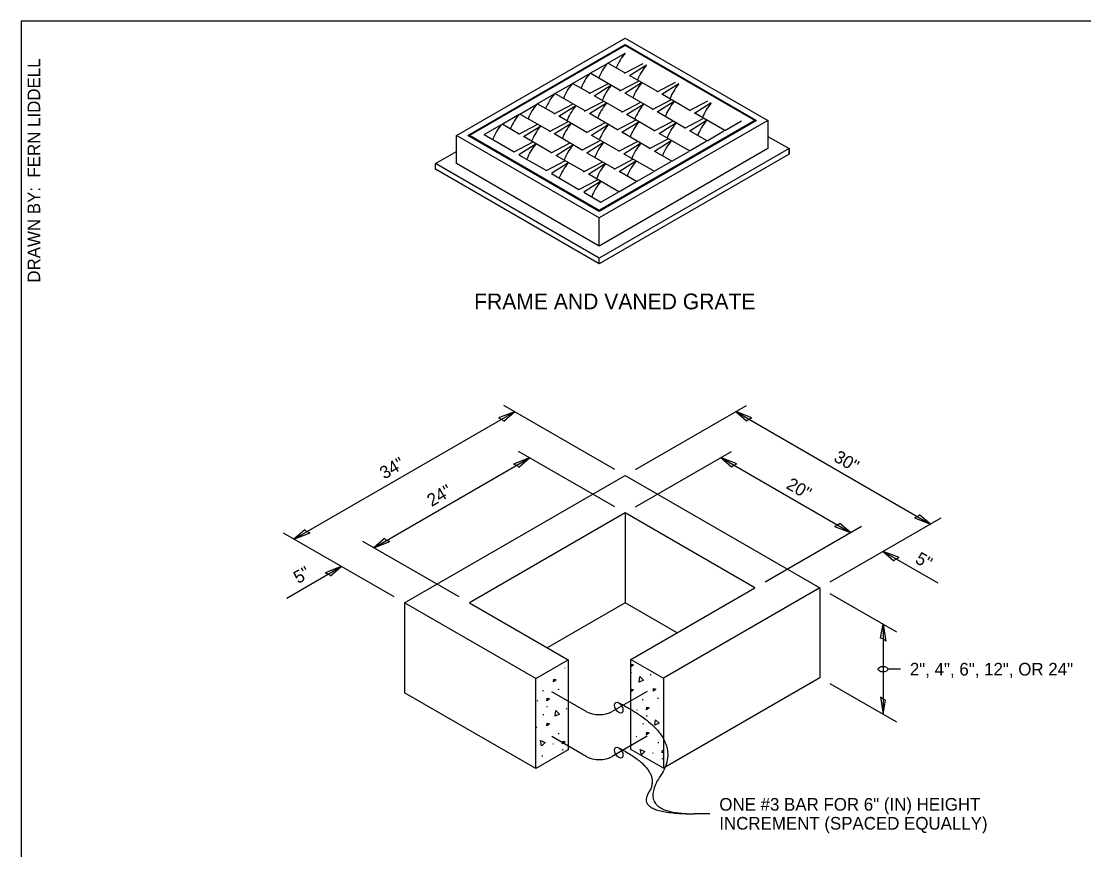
# Model space of a CAD drawing. Extents: x 99862 to 103151, y 100000 to 102076.
# Drawn here: x 99862 to 101209, y 101025 to 102076 of the extents above; entities that cross this region are included whole.
import ezdxf

# ---------------------------------------------------------------- set-up
doc = ezdxf.new("R2010")
doc.units = 0
for name, color, linetype in [('Level 1', 7, 'Continuous'), ('Level 12', 7, 'Continuous'), ('Level 13', 7, 'Continuous'), ('Level 15', 7, 'Continuous'), ('Level 17', 7, 'Continuous'), ('Level 20', 7, 'Continuous'), ('Level 3', 7, 'Continuous'), ('Level 62', 7, 'Continuous'), ('Level 8', 7, 'Continuous'), ('Level 9', 7, 'Continuous')]:
    doc.layers.add(name, color=color, linetype=linetype)

msp = doc.modelspace()

# ---------------------------------------------------------------- linework, layer by layer
at = {"layer": 'Level 1'}
for p, q in [((100347.8, 101338.4), (100627.5, 101499.9)), ((100627.5, 101499.9), (100874.3, 101357.4)), ((100627.5, 101452.4), (100430.1, 101338.4)), ((100627.5, 101452.4), (100627.5, 101395.4)), ((100792, 101357.4), (100627.5, 101452.4)), ((100627.5, 101395.4), (100627.5, 101338.4)), ((100634.8, 101266.6), (100792, 101357.4)), ((100874.3, 101357.4), (100675.9, 101242.8)), ((100874.3, 101357.4), (100874.3, 101300.4)), ((100347.8, 101338.4), (100347.8, 101281.4)), ((100514.1, 101242.4), (100347.8, 101338.4)), ((100430.1, 101338.4), (100555.3, 101266.1)), ((100627.5, 101338.4), (100528.8, 101281.4)), ((100693.3, 101300.4), (100627.5, 101338.4)), ((100874.3, 101300.4), (100874.3, 101243.4)), ((100347.8, 101281.4), (100347.8, 101224.4)), ((100874.3, 101243.4), (100675.9, 101128.9)), ((100514.1, 101128.4), (100347.8, 101224.4))]:
    msp.add_line(p, q, dxfattribs=at)
msp.add_lwpolyline([(99862, 99999.5), (103151, 99999.5), (103151, 102075.5), (99862, 102075.5)], close=True, dxfattribs=at)
at = {"layer": 'Level 12'}
for p, q in [((100627.5, 102044.7), (100430.1, 101930.7)), ((100792, 101949.7), (100627.5, 102044.7)), ((100605.6, 102022.5), (100627.3, 102035)), ((100583.2, 102009.6), (100604.9, 102022.1)), ((100627.2, 102010), (100605.6, 102022.5)), ((100626.8, 102009.8), (100650.1, 102022.1)), ((100654.3, 102019.7), (100632.9, 102006.2)), ((100560.9, 101996.7), (100582.6, 102009.2)), ((100621.3, 101987.6), (100583.2, 102009.6)), ((100668.3, 101986.3), (100633.6, 102006.3)), ((100538.5, 101983.8), (100560.2, 101996.3)), ((100582.5, 101984.2), (100560.9, 101996.7)), ((100582, 101984), (100605.4, 101996.3)), ((100609.5, 101993.9), (100588.2, 101980.4)), ((100620.8, 101987.4), (100644.2, 101999.7)), ((100648.3, 101997.3), (100627, 101983.8)), ((100667.9, 101986), (100691.3, 101998.4)), ((100695.4, 101996), (100674.1, 101982.5)), ((100516.1, 101970.9), (100537.8, 101983.4)), ((100576.6, 101961.8), (100538.5, 101983.8)), ((100576.1, 101961.6), (100599.5, 101973.9)), ((100623.6, 101960.5), (100588.9, 101980.5)), ((100662.4, 101963.9), (100627.7, 101983.9)), ((100662, 101963.6), (100685.4, 101976)), ((100689.5, 101973.6), (100668.1, 101960.1)), ((100709.5, 101962.5), (100674.8, 101982.6)), ((100709, 101962.3), (100732.4, 101974.6)), ((100493.8, 101957.9), (100515.5, 101970.5)), ((100537.7, 101958.4), (100516.1, 101970.9)), ((100537.3, 101958.1), (100560.7, 101970.5)), ((100564.8, 101968.1), (100543.5, 101954.6)), ((100603.6, 101971.5), (100582.3, 101958)), ((100623.2, 101960.2), (100646.5, 101972.5)), ((100650.7, 101970.2), (100629.3, 101956.7)), ((100703.5, 101940.1), (100668.8, 101960.2)), ((100736.5, 101972.2), (100715.2, 101958.7)), ((100471.4, 101945), (100493.1, 101957.6)), ((100531.8, 101936), (100493.8, 101957.9)), ((100531.4, 101935.7), (100554.8, 101948.1)), ((100578.9, 101934.6), (100544.2, 101954.7)), ((100578.4, 101934.4), (100601.8, 101946.7)), ((100617.7, 101938), (100583, 101958.1)), ((100792, 101949.7), (100594.6, 101835.7)), ((100617.2, 101937.8), (100640.6, 101950.1)), ((100644.7, 101947.8), (100623.4, 101934.3)), ((100664.7, 101936.7), (100630, 101956.7)), ((100664.3, 101936.5), (100687.7, 101948.8)), ((100691.8, 101946.4), (100670.5, 101932.9)), ((100703.1, 101939.9), (100726.5, 101952.2)), ((100730.6, 101949.8), (100709.3, 101936.3)), ((100753.7, 101937), (100715.9, 101958.8)), ((100753.7, 101937), (100775.1, 101949.4)), ((100792, 101949.7), (100791.9, 101948.4)), ((100448.6, 101931.9), (100470.7, 101944.7)), ((100493, 101932.6), (100471.4, 101945)), ((100492.6, 101932.3), (100516, 101944.6)), ((100520.1, 101942.3), (100498.7, 101928.8)), ((100558.9, 101945.7), (100537.5, 101932.2)), ((100605.9, 101944.3), (100584.6, 101930.8)), ((100658.8, 101914.3), (100624.1, 101934.3)), ((100708.9, 101911.2), (100671.2, 101933)), ((100731.3, 101924.1), (100710, 101936.4)), ((100731.3, 101924.1), (100752.7, 101936.5)), ((100594.6, 101835.7), (100430.1, 101930.7)), ((100430.3, 101929.4), (100430.1, 101930.7)), ((100448.6, 101931.9), (100486.6, 101909.9)), ((100486.6, 101909.9), (100510, 101922.2)), ((100514.2, 101919.9), (100492.8, 101906.3)), ((100534.1, 101908.8), (100499.4, 101928.8)), ((100533.7, 101908.6), (100557.1, 101920.9)), ((100573, 101912.2), (100538.3, 101932.3)), ((100572.5, 101912), (100595.9, 101924.3)), ((100600, 101921.9), (100578.7, 101908.4)), ((100620, 101910.9), (100585.3, 101930.9)), ((100619.6, 101910.7), (100642.9, 101923)), ((100647.1, 101920.6), (100625.7, 101907.1)), ((100658.4, 101914.1), (100681.8, 101926.4)), ((100685.9, 101924), (100664.5, 101910.5)), ((100708.9, 101911.2), (100730.3, 101923.6)), ((100492.8, 101906.3), (100527.8, 101886.2)), ((100561.2, 101918.5), (100539.9, 101905)), ((100614.1, 101888.5), (100579.4, 101908.5)), ((100664.2, 101885.4), (100626.4, 101907.2)), ((100686.6, 101898.3), (100665.2, 101910.6)), ((100686.6, 101898.3), (100708, 101910.6)), ((100527.8, 101886.2), (100551.2, 101898.5)), ((100555.3, 101896.1), (100534, 101882.6)), ((100575.3, 101885.1), (100540.6, 101905.1)), ((100574.8, 101884.8), (100598.2, 101897.1)), ((100602.3, 101894.8), (100581, 101881.3)), ((100613.6, 101888.2), (100637, 101900.6)), ((100641.1, 101898.2), (100619.8, 101884.7)), ((100664.2, 101885.4), (100685.6, 101897.7)), ((100534, 101882.6), (100568.9, 101862.4)), ((100619.5, 101859.5), (100581.7, 101881.4)), ((100641.8, 101872.5), (100620.5, 101884.8)), ((100641.8, 101872.5), (100663.2, 101884.8)), ((100568.9, 101862.4), (100592.3, 101874.7)), ((100596.4, 101872.4), (100575.1, 101858.9)), ((100619.5, 101859.5), (100640.9, 101871.9)), ((100575.1, 101858.9), (100596.7, 101846.4)), ((100596.7, 101846.4), (100618.5, 101859)), ((100594.6, 101834.5), (100594.6, 101835.7))]:
    msp.add_line(p, q, dxfattribs=at)
for centre, major_axis, ratio, start_param, end_param in [((100641.1, 102010.3), (17.8, 36.7), 0.619773, 1.161599, 1.703913), ((100618.7, 101997.4), (17.8, 36.7), 0.619773, 1.161599, 1.703913), ((100666.2, 101995.8), (17.9, 36.6), 0.569297, 1.174658, 1.709128), ((100596.4, 101984.5), (17.8, 36.7), 0.619773, 1.161599, 1.703913), ((100633, 102005), (0.64, 1.31), 0.569297, 6.243649, 7.029047), ((100574, 101971.6), (17.8, 36.7), 0.619773, 1.161599, 1.703913), ((100621.5, 101970), (17.9, 36.6), 0.569297, 1.174658, 1.709128), ((100660.3, 101973.4), (17.9, 36.6), 0.569297, 1.174658, 1.709128), ((100648.4, 101996.1), (0.64, 1.31), 0.569297, 0.745861, 1.174658), ((100707.3, 101972.1), (17.9, 36.6), 0.569297, 1.174658, 1.709128), ((100695.4, 101994.8), (0.64, 1.31), 0.569297, 0.745861, 1.174658), ((100551.6, 101958.7), (17.8, 36.7), 0.619773, 1.161599, 1.703913), ((100588.2, 101979.2), (0.64, 1.31), 0.569297, 6.243649, 7.029047), ((100627, 101982.6), (0.64, 1.31), 0.569297, 6.243649, 7.029047), ((100674.1, 101981.3), (0.64, 1.31), 0.569297, 6.243649, 7.029047), ((100701.4, 101949.7), (17.9, 36.6), 0.569297, 1.174658, 1.709128), ((100689.5, 101972.4), (0.64, 1.31), 0.569297, 0.745861, 1.174658), ((100529.3, 101945.8), (17.8, 36.7), 0.619773, 1.161599, 1.703913), ((100576.7, 101944.2), (17.9, 36.6), 0.569297, 1.174658, 1.709128), ((100615.6, 101947.6), (17.9, 36.6), 0.569297, 1.174658, 1.709128), ((100603.7, 101970.3), (0.64, 1.31), 0.569297, 0.745861, 1.174658), ((100662.6, 101946.3), (17.9, 36.6), 0.569297, 1.174658, 1.709128), ((100650.7, 101969), (0.64, 1.31), 0.569297, 0.745861, 1.174658), ((100668.2, 101958.9), (0.64, 1.31), 0.569297, 6.243649, 7.029047), ((100748.5, 101948.3), (17.9, 36.6), 0.569297, 1.174658, 1.709128), ((100736.6, 101971), (0.64, 1.31), 0.569297, 0.745861, 1.174658), ((100506.9, 101932.9), (17.8, 36.7), 0.619773, 1.161599, 1.703913), ((100543.5, 101953.4), (0.64, 1.31), 0.569297, 6.243649, 7.029047), ((100582.3, 101956.8), (0.64, 1.31), 0.569297, 6.243649, 7.029047), ((100629.4, 101955.5), (0.64, 1.31), 0.569297, 6.243649, 7.029047), ((100656.7, 101923.9), (17.9, 36.6), 0.569297, 1.174658, 1.709128), ((100644.8, 101946.5), (0.64, 1.31), 0.569297, 0.745861, 1.174658), ((100691.8, 101945.2), (0.64, 1.31), 0.569297, 0.745861, 1.174658), ((100715.2, 101957.5), (0.64, 1.31), 0.569297, 6.243649, 7.029047), ((100742.5, 101925.9), (17.9, 36.6), 0.569297, 1.174658, 1.709128), ((100730.6, 101948.6), (0.64, 1.31), 0.569297, 0.745861, 1.174658), ((100484.5, 101919.9), (17.8, 36.7), 0.619773, 1.161599, 1.714552), ((100532, 101918.4), (17.9, 36.6), 0.569297, 1.174658, 1.709128), ((100570.8, 101921.8), (17.9, 36.6), 0.569297, 1.174658, 1.709128), ((100558.9, 101944.5), (0.64, 1.31), 0.569297, 0.745861, 1.174658), ((100617.9, 101920.4), (17.9, 36.6), 0.569297, 1.174658, 1.709128), ((100606, 101943.1), (0.64, 1.31), 0.569297, 0.745861, 1.174658), ((100623.4, 101933), (0.64, 1.31), 0.569297, 6.243649, 7.029047), ((100670.5, 101931.7), (0.64, 1.31), 0.569297, 6.243649, 7.029047), ((100703.7, 101922.5), (17.9, 36.6), 0.569297, 1.174658, 1.709128), ((100709.3, 101935.1), (0.64, 1.31), 0.569297, 6.243649, 7.029047), ((100498.8, 101927.6), (0.64, 1.31), 0.569297, 6.243649, 7.029047), ((100526.1, 101895.9), (17.9, 36.6), 0.569297, 1.174658, 1.719767), ((100514.2, 101918.6), (0.64, 1.31), 0.569297, 0.745861, 1.174658), ((100537.6, 101931), (0.64, 1.31), 0.569297, 6.243649, 7.029047), ((100584.6, 101929.6), (0.64, 1.31), 0.569297, 6.243649, 7.029047), ((100612, 101898), (17.9, 36.6), 0.569297, 1.174658, 1.709128), ((100600.1, 101920.7), (0.64, 1.31), 0.569297, 0.745861, 1.174658), ((100659, 101896.7), (17.9, 36.6), 0.569297, 1.174658, 1.709128), ((100647.1, 101919.4), (0.64, 1.31), 0.569297, 0.745861, 1.174658), ((100697.8, 101900.1), (17.9, 36.6), 0.569297, 1.174658, 1.709128), ((100685.9, 101922.8), (0.64, 1.31), 0.569297, 0.745861, 1.174658), ((100573.1, 101894.6), (17.9, 36.6), 0.569297, 1.174658, 1.709128), ((100561.2, 101917.3), (0.64, 1.31), 0.569297, 0.745861, 1.174658), ((100578.7, 101907.2), (0.64, 1.31), 0.569297, 6.243649, 7.029047), ((100625.8, 101905.9), (0.64, 1.31), 0.569297, 6.243649, 7.029047), ((100664.6, 101909.3), (0.64, 1.31), 0.569297, 6.243649, 7.029047), ((100539.9, 101903.8), (0.64, 1.31), 0.569297, 6.243649, 7.029047), ((100567.2, 101872.2), (17.9, 36.6), 0.569297, 1.174658, 1.719767), ((100555.3, 101894.9), (0.64, 1.31), 0.569297, 0.745861, 1.174658), ((100614.3, 101870.9), (17.9, 36.6), 0.569297, 1.174658, 1.709128), ((100602.4, 101893.6), (0.64, 1.31), 0.569297, 0.745861, 1.174658), ((100653.1, 101874.3), (17.9, 36.6), 0.569297, 1.174658, 1.709128), ((100641.2, 101897), (0.64, 1.31), 0.569297, 0.745861, 1.174658), ((100581, 101880.1), (0.64, 1.31), 0.569297, 6.243649, 7.029047), ((100619.8, 101883.5), (0.64, 1.31), 0.569297, 6.243649, 7.029047), ((100608.4, 101848.5), (17.9, 36.6), 0.569297, 1.174658, 1.719767), ((100596.5, 101871.2), (0.64, 1.31), 0.569297, 0.745861, 1.174658)]:
    msp.add_ellipse(centre, major_axis=major_axis, ratio=ratio, start_param=start_param, end_param=end_param, dxfattribs=at)
at = {"layer": 'Level 13'}
for p, q in [((100550.8, 101256), (100551.5, 101255.5)), ((100634.8, 101249.9), (100635, 101249.7)), ((100634.9, 101250.2), (100635.6, 101249.6)), ((100659.8, 101246.7), (100659.9, 101247.9)), ((100523.6, 101226.4), (100523.7, 101227.6)), ((100543.1, 101228.1), (100543.2, 101229.3)), ((100516, 101214.9), (100516.5, 101213.9)), ((100527.8, 101207.2), (100528.5, 101206.7)), ((100528.4, 101207.1), (100529.1, 101206.6)), ((100649.9, 101214.9), (100650, 101216.2)), ((100669.4, 101216.6), (100669.5, 101217.8)), ((100524.1, 101196), (100524.1, 101197.2)), ((100553.3, 101203.6), (100553.4, 101204.8)), ((100642.3, 101203.4), (100642.8, 101202.4)), ((100654.2, 101195.7), (100654.9, 101195.2)), ((100654.7, 101195.6), (100655.5, 101195.1)), ((100514.7, 101181.1), (100515.4, 101180.6)), ((100650.4, 101184.5), (100650.5, 101185.8)), ((100543.4, 101171.9), (100543.5, 101173.1)), ((100641, 101169.6), (100641.8, 101169.1)), ((100535.8, 101160.3), (100536.3, 101159.3)), ((100547.7, 101152.6), (100548.4, 101152.1)), ((100548.2, 101152.5), (100548.9, 101152)), ((100669.8, 101160.4), (100669.9, 101161.6)), ((100522.5, 101143.5), (100522.6, 101144.7)), ((100662.2, 101148.8), (100662.7, 101147.8)), ((100674, 101141.1), (100674.8, 101140.6)), ((100674.6, 101141), (100675.3, 101140.5))]:
    msp.add_line(p, q, dxfattribs=at)
for points in [[(100514.1, 101242.4), (100555.3, 101266.1), (100555.3, 101152.1), (100514.1, 101128.4)], [(100514.1, 101242.4), (100555.3, 101266.1), (100555.3, 101152.1), (100514.1, 101128.4)], [(100634.8, 101266.6), (100675.9, 101242.8), (100675.9, 101128.9), (100634.8, 101152.6)], [(100634.8, 101266.6), (100675.9, 101242.8), (100675.9, 101128.9), (100634.8, 101152.6)]]:
    msp.add_lwpolyline(points, close=True, dxfattribs=at)
for points in [[(100634.8, 101257.3), (100635.1, 101260.8), (100638.1, 101259.9), (100634.8, 101257.3)], [(100536.8, 101238.1), (100537.2, 101241.5), (100540.1, 101240.6), (100536.8, 101238.1)], [(100645.2, 101237.8), (100646.2, 101244.9), (100650.6, 101240.3), (100645.3, 101237.9)], [(100634.8, 101227.6), (100634.9, 101229), (100637.9, 101228.1), (100634.8, 101225.8)], [(100663.2, 101226.6), (100663.5, 101230), (100666.5, 101229.1), (100663.2, 101226.6)], [(100528.3, 101214.2), (100528.6, 101217.7), (100531.6, 101216.8), (100528.3, 101214.2)], [(100654.6, 101202.8), (100655, 101206.2), (100658, 101205.3), (100654.6, 101202.8)], [(100538.7, 101194.7), (100539.7, 101201.8), (100544.1, 101197.2), (100538.8, 101194.8)], [(100528, 101182.5), (100528.4, 101186), (100531.4, 101185.1), (100528, 101182.5)], [(100665.1, 101183.2), (100666, 101190.3), (100670.5, 101185.7), (100665.2, 101183.3)], [(100654.4, 101171), (100654.8, 101174.5), (100657.7, 101173.6), (100654.4, 101171)], [(100521.6, 101157.1), (100520.1, 101164.1), (100525.9, 101161.3), (100521.7, 101157.2)], [(100548.1, 101159.7), (100548.5, 101163.1), (100551.4, 101162.2), (100548.1, 101159.7)], [(100648, 101145.6), (100646.5, 101152.6), (100652.3, 101149.8), (100648.1, 101145.7)], [(100674.5, 101148.2), (100674.8, 101151.6), (100675.9, 101151.3)], [(100675.9, 101149.2), (100674.5, 101148.2)]]:
    msp.add_lwpolyline(points, dxfattribs=at)
at = {"layer": 'Level 15'}
for p, q in [((100614.5, 101507.4), (100473.5, 101588.6)), ((100640.5, 101507.4), (100781.4, 101588.7)), ((100207.7, 101419.1), (100487.4, 101580.6)), ((100767.6, 101580.7), (101014.4, 101438.2)), ((100614.5, 101459.9), (100492.4, 101530.2)), ((100640.5, 101459.9), (100762.4, 101530.4)), ((100308.8, 101408.2), (100506.3, 101522.2)), ((100748.6, 101522.4), (100913.1, 101427.4)), ((100805, 101364.9), (100927, 101435.4)), ((100887.3, 101364.9), (101028.2, 101446.2)), ((100334.8, 101345.9), (100194.4, 101426.8)), ((100417.1, 101345.9), (100295, 101416.2)), ((100954.3, 101403.6), (101023.6, 101363.6)), ((100198.5, 101344.5), (100267.7, 101384.5)), ((100971.6, 101301.3), (100887.3, 101349.9)), ((100954.3, 101311.3), (100954.3, 101197.3)), ((100976.3, 101254.3), (100960.3, 101254.3)), ((100971.6, 101187.3), (100887.3, 101235.9)), ((100734.8, 101071), (100714.8, 101071))]:
    msp.add_line(p, q, dxfattribs=at)
for centre, major_axis in [((100954.3, 101254.3), (-6, 0)), ((100619.4, 101205.5), (-3.75, 6.5)), ((100619.4, 101148.5), (-3.75, 6.5))]:
    msp.add_ellipse(centre, major_axis=major_axis, ratio=0.57735, dxfattribs=at)
for points in [[(100619.2, 101211.7), (100705.1, 101168.3), (100639.8, 101071), (100714.8, 101071)], [(100619, 101154.8), (100675.2, 101125.8), (100639.8, 101071), (100714.8, 101071)]]:
    msp.add_open_spline(points, degree=2, dxfattribs=at)
at = {"layer": 'Level 17'}
for points in [[(100578.2, 101200.7), (100534.7, 101225.7)], [(100655.3, 101226.2), (100611.1, 101200.7)], [(100578.2, 101143.7), (100534.7, 101168.8)], [(100655.3, 101169.2), (100611.1, 101143.7)]]:
    msp.add_lwpolyline(points, dxfattribs=at)
for centre in [(100594.6, 101210.2), (100594.6, 101153.2)]:
    msp.add_ellipse(centre, major_axis=(-23.3, 0), ratio=0.57735, start_param=0.785398, end_param=2.356194, dxfattribs=at)
at = {"layer": 'Level 3'}
for p, q in [((100413.6, 101930.7), (100627.5, 102054.2)), ((100627.5, 102054.2), (100808.5, 101949.7)), ((100428, 101930.7), (100627.5, 102045.9)), ((100627.5, 102044.7), (100627.5, 102045.9)), ((100627.5, 102045.9), (100794.1, 101949.7)), ((100808.5, 101949.7), (100594.6, 101826.2)), ((100794.1, 101949.7), (100594.6, 101834.5)), ((100808.5, 101949.7), (100808.5, 101914.1)), ((100413.6, 101895.1), (100413.6, 101930.7)), ((100594.6, 101826.2), (100413.6, 101930.7)), ((100594.6, 101834.5), (100428, 101930.7)), ((100808.5, 101929.5), (100835.2, 101914.1)), ((100386.9, 101895.1), (100413.6, 101910.5)), ((100835.2, 101914.1), (100594.6, 101775.1)), ((100808.5, 101914.1), (100594.6, 101790.6)), ((100835.2, 101906.9), (100594.6, 101768)), ((100835.2, 101906.9), (100835.2, 101914.1)), ((100386.9, 101887.9), (100386.9, 101895.1)), ((100594.6, 101775.1), (100386.9, 101895.1)), ((100594.6, 101790.6), (100413.6, 101895.1)), ((100594.6, 101768), (100386.9, 101887.9)), ((100594.6, 101790.6), (100594.6, 101826.2)), ((100594.6, 101768), (100594.6, 101775.1))]:
    msp.add_line(p, q, dxfattribs=at)
at = {"layer": 'Level 8'}
for points in [[(100487.4, 101580.6), (100467, 101572.7), (100471.1, 101571.2), (100473.7, 101568.8)], [(100767.6, 101580.7), (100781.3, 101568.9), (100783.8, 101571.3), (100787.9, 101572.8)], [(100506.3, 101522.2), (100485.9, 101514.3), (100490, 101512.9), (100492.6, 101510.5)], [(100748.6, 101522.4), (100762.3, 101510.6), (100764.8, 101513), (100769, 101514.5)], [(101014.4, 101438.2), (101000.7, 101449.9), (100998.1, 101447.6), (100994, 101446.1)], [(100913.1, 101427.4), (100899.4, 101439.1), (100896.9, 101436.7), (100892.7, 101435.3)], [(100207.7, 101419.1), (100228, 101427), (100223.9, 101428.5), (100221.4, 101430.9)], [(100308.8, 101408.2), (100329.2, 101416.2), (100325.1, 101417.6), (100322.5, 101420)], [(100954.3, 101403.6), (100968, 101391.8), (100970.6, 101394.2), (100974.7, 101395.7)], [(100267.7, 101384.5), (100247.4, 101376.6), (100251.5, 101375.2), (100254.1, 101372.8)], [(100954.3, 101311.3), (100957.7, 101289.7), (100954.3, 101292.6), (100951, 101293.6)], [(100954.3, 101197.3), (100957.6, 101215.1), (100954.3, 101216.1), (100951, 101218.9)]]:
    msp.add_lwpolyline(points, close=True, dxfattribs=at)
at = {"layer": 'Level 9'}
msp.add_lwpolyline([(100413.6, 101910.5), (100413.6, 101930.7), (100627.5, 102054.2), (100808.5, 101949.7), (100808.5, 101929.5), (100835.2, 101914.1), (100835.2, 101906.9), (100594.6, 101768), (100386.9, 101887.9), (100386.9, 101895.1), (100413.6, 101910.5)], dxfattribs=at)

# ---------------------------------------------------------------- texts
at = {"layer": 'Level 20'}
msp.add_text('FRAME AND VANED GRATE', height=20, dxfattribs=at).set_placement((100436, 101710.4))
for s, rotation, p in [('30"', 330.0271, (100890.6, 101518.8)), ('34"', 29.9987, (100322.2, 101494.5)), ('24"', 29.9987, (100382.2, 101459.8)), ('20"', 330.0271, (100830.4, 101484.2)), ('5"', 330.0271, (100993.8, 101389.9)), ('5"', 29.9987, (100213, 101362.1)), ('2", 4", 6", 12", OR 24"', 360, (100988.3, 101246.3)), ('ONE #3 BAR FOR 6" (IN) HEIGHT', 360, (100746.8, 101075)), ('INCREMENT (SPACED EQUALLY)', 360, (100746.8, 101051))]:
    msp.add_text(s, height=16, rotation=rotation, dxfattribs=at).set_placement(p)
at = {"layer": 'Level 62'}
msp.add_text('DRAWN BY:  FERN LIDDELL', height=16, rotation=90, dxfattribs=at).set_placement((99886, 101744.2))

doc.saveas('drawing.dxf')
